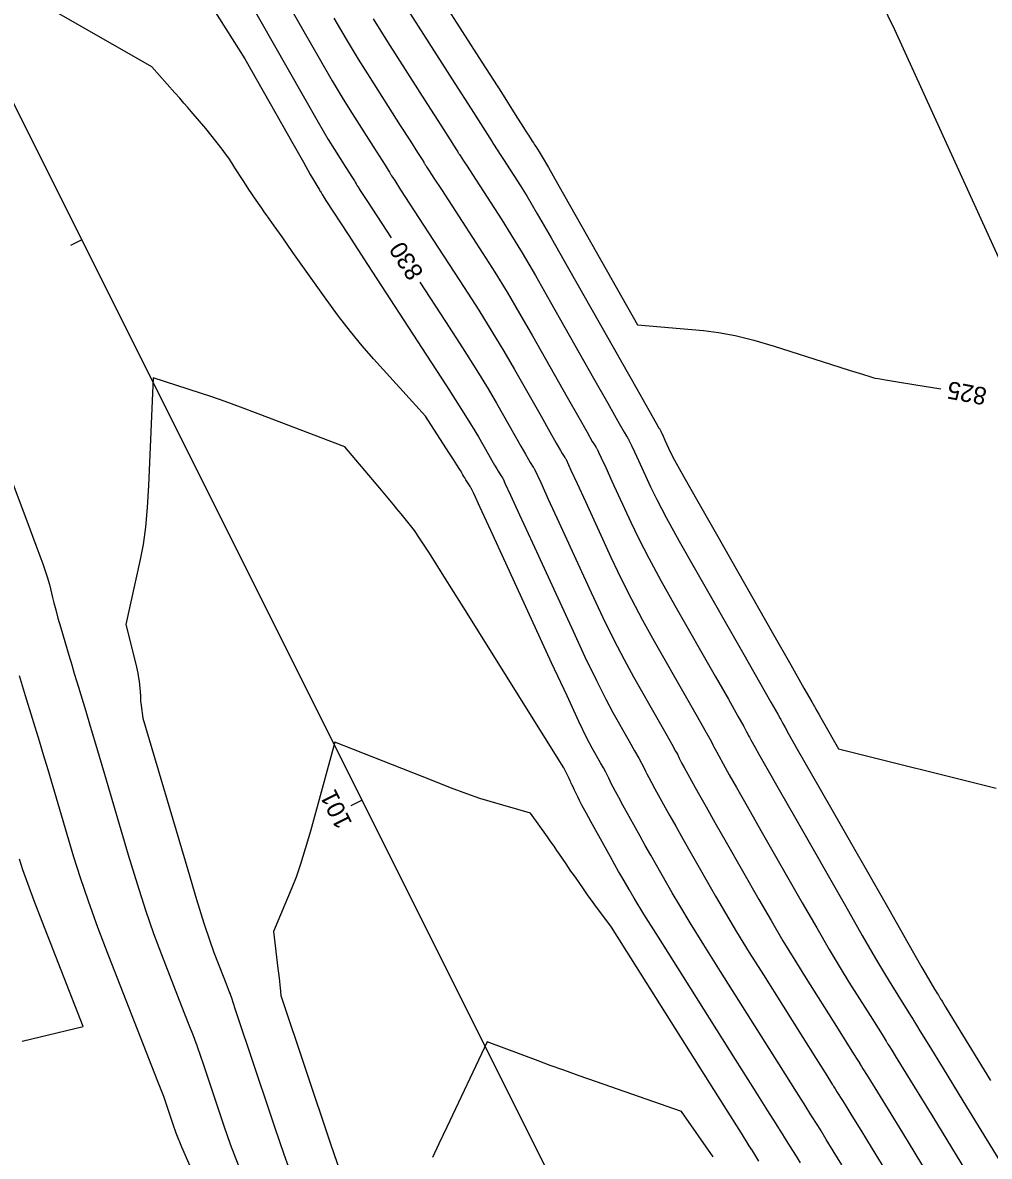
# Model space of a CAD drawing. Extents: x 1715724 to 1716561, y 394063 to 395906.
# Drawn here: x 1716294.8 to 1716371.9, y 394512.3 to 394602.7 of the extents above; entities that cross this region are included whole.
import ezdxf

# ---------------------------------------------------------------- set-up
doc = ezdxf.new("R2010")
doc.units = 0
for name, color, linetype in [('DT_X_Contour_Major', 7, 'Continuous'), ('DT_X_Contour_Minor', 7, 'Continuous'), ('DT_X_TIN_Hull', 7, 'Continuous'), ('GE_P_CL_10', 7, 'Continuous')]:
    doc.layers.add(name, color=color, linetype=linetype)

msp = doc.modelspace()

# ---------------------------------------------------------------- linework, layer by layer
at = {"layer": 'DT_X_Contour_Major'}
for points in [[(1716326.726, 394606.964), (1716331.443, 394599.586), (1716332.991, 394597.165), (1716334.098, 394595.434), (1716334.762, 394594.395), (1716334.985, 394594.046), (1716334.991, 394594.036), (1716335.003, 394594.017), (1716335.035, 394593.967), (1716335.087, 394593.885), (1716335.158, 394593.773), (1716335.376, 394593.433), (1716335.46, 394593.302), (1716335.55, 394593.162), (1716335.645, 394593.015), (1716335.746, 394592.86), (1716336.022, 394592.435), (1716336.255, 394592.043), (1716336.75, 394591.186), (1716337.504, 394589.863), (1716338.519, 394588.075), (1716343.863, 394578.642), (1716349.122, 394578.193), (1716350.319, 394578.042), (1716351.657, 394577.781), (1716353.136, 394577.41), (1716354.756, 394576.93), (1716359.263, 394575.503), (1716360.747, 394575.034), (1716361.82, 394574.696), (1716362.48, 394574.489), (1716362.728, 394574.414), (1716362.841, 394574.389), (1716363.065, 394574.35), (1716363.654, 394574.252), (1716364.608, 394574.096), (1716365.925, 394573.881), (1716368.057, 394573.535)], [(1716311.729, 394606.51), (1716315.871, 394599.191), (1716317.273, 394596.723), (1716318.373, 394594.806), (1716319.17, 394593.44), (1716319.665, 394592.626), (1716320.583, 394591.192), (1716321.113, 394590.36), (1716321.26, 394590.127), (1716321.328, 394590.016), (1716321.403, 394589.883), (1716321.43, 394589.836), (1716321.454, 394589.796), (1716321.475, 394589.761), (1716321.492, 394589.733), (1716321.535, 394589.667), (1716321.735, 394589.359), (1716322.304, 394588.484), (1716324.193, 394585.577)], [(1716326.482, 394582.056), (1716328.52, 394578.921), (1716329.893, 394576.795), (1716331.03, 394575), (1716331.931, 394573.535), (1716332.597, 394572.402), (1716334.059, 394569.821), (1716334.548, 394568.961), (1716334.916, 394568.316), (1716335.164, 394567.886), (1716335.292, 394567.672), (1716335.534, 394567.293), (1716335.579, 394567.222), (1716335.609, 394567.175), (1716335.623, 394567.151), (1716335.641, 394567.12), (1716336.134, 394566.052), (1716336.74, 394564.736), (1716337.586, 394562.897), (1716340.161, 394557.299), (1716341.097, 394555.303), (1716341.973, 394553.513), (1716342.789, 394551.931), (1716343.544, 394550.555), (1716345.48, 394547.161), (1716346.122, 394546.033), (1716346.596, 394545.193), (1716346.903, 394544.641), (1716347.043, 394544.379), (1716347.191, 394544.063), (1716347.271, 394543.902), (1716347.4, 394543.659), (1716347.577, 394543.333), (1716348.468, 394541.721), (1716348.809, 394541.112), (1716349.333, 394540.185), (1716350.04, 394538.943), (1716350.929, 394537.383), (1716353.545, 394532.803), (1716354.516, 394531.12), (1716355.469, 394529.507), (1716356.404, 394527.964), (1716357.32, 394526.491), (1716359.739, 394522.657), (1716361.103, 394520.494), (1716361.448, 394519.946), (1716361.568, 394519.755), (1716361.589, 394519.719), (1716361.611, 394519.682), (1716361.744, 394519.471), (1716361.854, 394519.295), (1716362.188, 394518.766), (1716362.458, 394518.33), (1716363.017, 394517.419), (1716363.866, 394516.033), (1716365.005, 394514.172), (1716368.426, 394508.576)], [(1716294.75, 394521.492), (1716299.62, 394522.654), (1716296.349, 394531.037), (1716295.71, 394532.694), (1716295.195, 394534.074), (1716294.806, 394535.176), (1716294.54, 394536.001)], [(1716349.893, 394512.258), (1716347.371, 394515.883), (1716340.593, 394518.247), (1716339.213, 394518.731), (1716337.978, 394519.17), (1716336.887, 394519.564), (1716335.941, 394519.913), (1716331.863, 394521.435), (1716328.645, 394514.631), (1716328.013, 394513.299), (1716327.498, 394512.22)]]:
    msp.add_lwpolyline(points, dxfattribs=at)
at = {"layer": 'DT_X_Contour_Minor'}
for points in [[(1716313.779, 394608.135), (1716317.231, 394602.036), (1716318.442, 394599.912), (1716319.487, 394598.113), (1716320.365, 394596.641), (1716321.078, 394595.494), (1716322.755, 394592.871), (1716323.71, 394591.375), (1716323.96, 394590.98), (1716324.059, 394590.822), (1716324.121, 394590.714), (1716324.145, 394590.672), (1716324.17, 394590.63), (1716324.197, 394590.586), (1716324.225, 394590.541), (1716324.303, 394590.42), (1716324.48, 394590.147), (1716324.953, 394589.419), (1716326.787, 394586.598), (1716330.021, 394581.624), (1716331.181, 394579.817), (1716332.237, 394578.124), (1716333.189, 394576.548), (1716334.037, 394575.086), (1716336.157, 394571.344), (1716336.86, 394570.105), (1716337.377, 394569.196), (1716337.709, 394568.617), (1716337.855, 394568.368), (1716338.047, 394568.067), (1716338.085, 394568.008), (1716338.111, 394567.966), (1716338.126, 394567.94), (1716338.152, 394567.895), (1716338.548, 394567.038), (1716339.03, 394565.993), (1716339.7, 394564.536), (1716341.739, 394560.104), (1716342.529, 394558.438), (1716343.368, 394556.765), (1716344.257, 394555.086), (1716345.196, 394553.399), (1716347.767, 394548.891), (1716348.615, 394547.401), (1716349.233, 394546.311), (1716349.621, 394545.621), (1716349.779, 394545.331), (1716349.891, 394545.092), (1716349.952, 394544.97), (1716350.049, 394544.786), (1716350.183, 394544.539), (1716350.859, 394543.318), (1716351.178, 394542.749), (1716351.76, 394541.724), (1716352.602, 394540.245), (1716353.706, 394538.31), (1716356.999, 394532.543), (1716358.159, 394530.525), (1716359.168, 394528.797), (1716360.027, 394527.358), (1716360.736, 394526.209), (1716362.426, 394523.53), (1716363.381, 394522.015), (1716363.624, 394521.629), (1716363.711, 394521.489), (1716363.736, 394521.446), (1716363.755, 394521.414), (1716363.851, 394521.26), (1716363.929, 394521.136), (1716364.162, 394520.767), (1716364.431, 394520.331), (1716365.064, 394519.299), (1716367.419, 394515.449), (1716371.528, 394508.729)], [(1716308.987, 394605.477), (1716312.517, 394599.871), (1716316.45, 394592.922), (1716317.194, 394591.607), (1716317.743, 394590.642), (1716318.096, 394590.026), (1716318.253, 394589.759), (1716318.466, 394589.425), (1716318.516, 394589.345), (1716318.559, 394589.273), (1716318.596, 394589.21), (1716318.686, 394589.052), (1716318.738, 394588.962), (1716318.752, 394588.937), (1716318.759, 394588.925), (1716318.766, 394588.914), (1716318.99, 394588.57), (1716320.76, 394585.847), (1716322.307, 394583.468), (1716327.02, 394576.219), (1716328.604, 394573.773), (1716329.822, 394571.875), (1716330.673, 394570.523), (1716331.158, 394569.717), (1716331.962, 394568.298), (1716332.236, 394567.816), (1716332.455, 394567.435), (1716332.62, 394567.155), (1716332.729, 394566.976), (1716332.949, 394566.633), (1716333.021, 394566.52), (1716333.074, 394566.437), (1716333.107, 394566.385), (1716333.12, 394566.363), (1716333.13, 394566.345), (1716333.28, 394566.022), (1716333.719, 394565.067), (1716334.45, 394563.479), (1716335.472, 394561.258), (1716338.584, 394554.494), (1716339.666, 394552.167), (1716340.578, 394550.261), (1716341.32, 394548.776), (1716341.893, 394547.711), (1716343.193, 394545.431), (1716343.628, 394544.664), (1716343.959, 394544.074), (1716344.185, 394543.662), (1716344.306, 394543.426), (1716344.491, 394543.033), (1716344.591, 394542.834), (1716344.75, 394542.532), (1716344.97, 394542.127), (1716345.25, 394541.618), (1716346.077, 394540.124), (1716346.44, 394539.474), (1716346.906, 394538.647), (1716347.477, 394537.641), (1716348.152, 394536.457), (1716350.09, 394533.062), (1716350.874, 394531.714), (1716351.771, 394530.217), (1716352.781, 394528.57), (1716353.905, 394526.774), (1716357.052, 394521.784), (1716358.086, 394520.145), (1716358.826, 394518.972), (1716359.272, 394518.264), (1716359.425, 394518.02), (1716359.441, 394517.992), (1716359.467, 394517.951), (1716359.532, 394517.847), (1716359.636, 394517.682), (1716359.779, 394517.454), (1716360.214, 394516.765), (1716360.485, 394516.329), (1716360.971, 394515.539), (1716361.673, 394514.394), (1716362.59, 394512.895), (1716365.324, 394508.424)], [(1716325.314, 394604.097), (1716329.271, 394597.907), (1716330.571, 394595.875), (1716332.062, 394593.541), (1716332.254, 394593.24), (1716332.273, 394593.205), (1716332.288, 394593.181), (1716332.319, 394593.132), (1716332.425, 394592.965), (1716332.608, 394592.68), (1716332.715, 394592.513), (1716332.901, 394592.227), (1716333.164, 394591.82), (1716334.521, 394589.733), (1716335.047, 394588.881), (1716335.86, 394587.499), (1716336.963, 394585.585), (1716338.354, 394583.14), (1716343.795, 394573.538), (1716344.759, 394571.837), (1716345.342, 394570.81), (1716345.544, 394570.455), (1716345.574, 394570.407), (1716345.601, 394570.364), (1716345.617, 394570.337), (1716345.634, 394570.306), (1716345.683, 394570.219), (1716345.72, 394570.147), (1716345.899, 394569.764), (1716346.043, 394569.453), (1716346.473, 394568.519), (1716346.824, 394567.844), (1716347.554, 394566.521), (1716348.663, 394564.55), (1716350.152, 394561.931), (1716354.627, 394554.083), (1716356.096, 394551.507), (1716357.146, 394549.666), (1716357.776, 394548.56), (1716357.987, 394548.189), (1716357.992, 394548.179), (1716357.994, 394548.175), (1716357.998, 394548.167), (1716358.003, 394548.157), (1716358.01, 394548.145), (1716358.03, 394548.109), (1716358.072, 394548.036), (1716358.182, 394547.843), (1716358.359, 394547.532), (1716358.606, 394547.101), (1716359.913, 394544.811), (1716372.498, 394541.671)], [(1716360.176, 394511.618), (1716359.48, 394512.755), (1716358.925, 394513.659), (1716358.511, 394514.329), (1716358.24, 394514.764), (1716357.704, 394515.613), (1716357.528, 394515.893), (1716357.401, 394516.094), (1716357.323, 394516.219), (1716357.294, 394516.265), (1716357.282, 394516.286), (1716357.096, 394516.581), (1716356.549, 394517.45), (1716355.638, 394518.894), (1716354.366, 394520.911), (1716350.489, 394527.056), (1716349.158, 394529.176), (1716348.072, 394530.927), (1716347.231, 394532.309), (1716346.635, 394533.322), (1716345.374, 394535.531), (1716344.914, 394536.339), (1716344.479, 394537.108), (1716344.07, 394537.837), (1716343.687, 394538.527), (1716342.698, 394540.313), (1716342.363, 394540.921), (1716342.101, 394541.405), (1716341.91, 394541.766), (1716341.791, 394542.004), (1716341.57, 394542.474), (1716341.466, 394542.682), (1716341.321, 394542.956), (1716341.134, 394543.296), (1716340.906, 394543.7), (1716340.241, 394544.866), (1716339.851, 394545.621), (1716339.183, 394547.009), (1716338.234, 394549.032), (1716337.006, 394551.689), (1716333.358, 394559.619), (1716332.16, 394562.222), (1716331.305, 394564.081), (1716330.792, 394565.197), (1716330.62, 394565.57), (1716330.618, 394565.574), (1716330.605, 394565.594), (1716330.568, 394565.651), (1716330.508, 394565.746), (1716330.423, 394565.878), (1716330.166, 394566.281), (1716330.075, 394566.425), (1716329.995, 394566.555), (1716329.924, 394566.672), (1716329.864, 394566.775), (1716329.719, 394567.033), (1716329.62, 394567.194), (1716329.435, 394567.487), (1716329.164, 394567.909), (1716328.805, 394568.463), (1716326.928, 394571.349), (1716322.786, 394575.931), (1716321.885, 394576.965), (1716320.956, 394578.104), (1716320, 394579.347), (1716319.017, 394580.694), (1716316.36, 394584.426), (1716315.487, 394585.653), (1716314.86, 394586.533), (1716314.481, 394587.066), (1716314.349, 394587.253), (1716314.325, 394587.291), (1716314.29, 394587.342), (1716314.203, 394587.467), (1716314.064, 394587.667), (1716313.872, 394587.941), (1716313.291, 394588.769), (1716313.07, 394589.089), (1716312.843, 394589.427), (1716312.611, 394589.784), (1716312.372, 394590.158), (1716311.728, 394591.181), (1716311.482, 394591.561), (1716311.228, 394591.933), (1716310.966, 394592.298), (1716310.694, 394592.655), (1716309.41, 394594.306), (1716308.234, 394595.673), (1716307.965, 394595.985), (1716307.66, 394596.336), (1716307.318, 394596.725), (1716306.942, 394597.151), (1716305.1, 394599.233), (1716297.709, 394603.453)], [(1716319.611, 394603.101), (1716320.601, 394601.421), (1716321.561, 394599.841), (1716322.49, 394598.362), (1716324.927, 394594.55), (1716325.729, 394593.295), (1716326.307, 394592.39), (1716326.661, 394591.834), (1716326.791, 394591.628), (1716326.838, 394591.544), (1716326.859, 394591.508), (1716326.886, 394591.464), (1716326.919, 394591.411), (1716326.959, 394591.349), (1716327.071, 394591.173), (1716327.225, 394590.936), (1716327.602, 394590.355), (1716328.203, 394589.431), (1716329.026, 394588.164), (1716331.521, 394584.327), (1716332.47, 394582.838), (1716333.445, 394581.249), (1716334.447, 394579.56), (1716335.476, 394577.771), (1716338.255, 394572.866), (1716339.171, 394571.249), (1716339.837, 394570.076), (1716340.253, 394569.348), (1716340.418, 394569.064), (1716340.524, 394568.898), (1716340.56, 394568.84), (1716340.59, 394568.793), (1716340.613, 394568.756), (1716340.629, 394568.729), (1716340.662, 394568.67), (1716340.744, 394568.497), (1716340.963, 394568.024), (1716341.32, 394567.25), (1716341.814, 394566.175), (1716343.317, 394562.909), (1716343.96, 394561.573), (1716344.763, 394560.017), (1716345.726, 394558.241), (1716346.848, 394556.243), (1716350.054, 394550.622), (1716351.109, 394548.77), (1716351.871, 394547.429), (1716352.34, 394546.601), (1716352.515, 394546.284), (1716352.592, 394546.121), (1716352.633, 394546.039), (1716352.699, 394545.913), (1716352.79, 394545.745), (1716352.906, 394545.534), (1716353.249, 394544.915), (1716353.548, 394544.386), (1716354.186, 394543.263), (1716355.165, 394541.546), (1716356.484, 394539.236), (1716360.454, 394532.283), (1716361.801, 394529.931), (1716362.867, 394528.087), (1716363.65, 394526.752), (1716364.152, 394525.926), (1716365.113, 394524.403), (1716365.429, 394523.901), (1716365.658, 394523.537), (1716365.8, 394523.311), (1716365.855, 394523.223), (1716365.883, 394523.173), (1716365.899, 394523.146), (1716365.924, 394523.105), (1716365.959, 394523.049), (1716366.004, 394522.977), (1716366.136, 394522.768), (1716366.404, 394522.331), (1716367.11, 394521.179), (1716368.253, 394519.31), (1716369.833, 394516.726), (1716374.631, 394508.881)], [(1716322.756, 394603.042), (1716323.902, 394601.229), (1716327.099, 394596.229), (1716328.15, 394594.585), (1716328.904, 394593.405), (1716329.361, 394592.688), (1716329.522, 394592.434), (1716329.556, 394592.375), (1716329.574, 394592.344), (1716329.602, 394592.298), (1716329.642, 394592.236), (1716329.692, 394592.157), (1716329.839, 394591.927), (1716329.97, 394591.724), (1716330.251, 394591.291), (1716330.683, 394590.626), (1716331.266, 394589.729), (1716333.021, 394587.03), (1716333.758, 394585.86), (1716334.653, 394584.374), (1716335.705, 394582.573), (1716336.915, 394580.455), (1716340.352, 394574.389), (1716341.483, 394572.394), (1716342.298, 394570.957), (1716342.798, 394570.079), (1716342.981, 394569.759), (1716343.049, 394569.652), (1716343.074, 394569.614), (1716343.095, 394569.579), (1716343.115, 394569.547), (1716343.131, 394569.518), (1716343.173, 394569.445), (1716343.232, 394569.322), (1716343.377, 394569.01), (1716343.61, 394568.507), (1716343.929, 394567.814), (1716344.895, 394565.714), (1716345.392, 394564.709), (1716346.158, 394563.269), (1716347.194, 394561.396), (1716348.5, 394559.087), (1716352.34, 394552.352), (1716353.603, 394550.138), (1716354.508, 394548.548), (1716355.058, 394547.58), (1716355.251, 394547.236), (1716355.292, 394547.15), (1716355.314, 394547.107), (1716355.349, 394547.04), (1716355.397, 394546.951), (1716355.458, 394546.84), (1716355.64, 394546.512), (1716355.917, 394546.023), (1716356.613, 394544.802), (1716357.728, 394542.848), (1716359.261, 394540.162), (1716363.908, 394532.024), (1716365.444, 394529.336), (1716366.566, 394527.377), (1716367.274, 394526.146), (1716367.567, 394525.644), (1716367.799, 394525.276), (1716367.877, 394525.153), (1716367.936, 394525.059), (1716367.976, 394524.993), (1716367.998, 394524.957), (1716368.03, 394524.899), (1716368.043, 394524.878), (1716368.055, 394524.857), (1716368.067, 394524.838), (1716368.079, 394524.818), (1716368.11, 394524.769), (1716368.194, 394524.633), (1716368.42, 394524.262), (1716368.79, 394523.657), (1716369.304, 394522.818), (1716372.033, 394518.354)], [(1716356.878, 394511.779), (1716356.538, 394512.328), (1716356.266, 394512.763), (1716355.629, 394513.772), (1716355.42, 394514.104), (1716355.27, 394514.342), (1716355.179, 394514.487), (1716355.147, 394514.539), (1716355.139, 394514.552), (1716354.921, 394514.899), (1716354.271, 394515.929), (1716353.191, 394517.642), (1716351.679, 394520.038), (1716347.073, 394527.339), (1716345.535, 394529.782), (1716344.373, 394531.637), (1716343.588, 394532.904), (1716343.181, 394533.582), (1716342.597, 394534.604), (1716342.351, 394535.037), (1716342.053, 394535.569), (1716341.701, 394536.2), (1716341.296, 394536.93), (1716340.146, 394539.007), (1716339.757, 394539.715), (1716339.451, 394540.278), (1716339.229, 394540.698), (1716339.091, 394540.975), (1716338.834, 394541.521), (1716338.748, 394541.703), (1716338.684, 394541.838), (1716338.641, 394541.927), (1716338.619, 394541.97), (1716338.589, 394542.022), (1716338.568, 394542.063), (1716338.529, 394542.146), (1716338.471, 394542.27), (1716338.394, 394542.437), (1716337.991, 394543.312), (1716329.949, 394556.15), (1716328.412, 394558.592), (1716327.25, 394560.419), (1716326.462, 394561.629), (1716326.049, 394562.222), (1716324.992, 394563.553), (1716324.63, 394563.997), (1716324.488, 394564.169), (1716324.215, 394564.494), (1716323.813, 394564.971), (1716323.28, 394565.602), (1716320.492, 394568.903), (1716313.569, 394571.543), (1716312.17, 394572.071), (1716310.938, 394572.523), (1716309.874, 394572.898), (1716308.978, 394573.198), (1716305.189, 394574.419), (1716304.824, 394565.823), (1716304.725, 394564.072), (1716304.583, 394562.504), (1716304.399, 394561.12), (1716304.173, 394559.918), (1716303.017, 394554.736), (1716303.729, 394551.886), (1716303.866, 394551.324), (1716303.969, 394550.859), (1716304.04, 394550.492), (1716304.079, 394550.221), (1716304.138, 394549.629), (1716304.158, 394549.426), (1716304.171, 394549.259), (1716304.179, 394549.13), (1716304.181, 394549.037), (1716304.179, 394548.84), (1716304.182, 394548.749), (1716304.193, 394548.622), (1716304.211, 394548.459), (1716304.237, 394548.261), (1716304.377, 394547.254), (1716307.962, 394535.155), (1716308.668, 394532.798), (1716309.251, 394530.914), (1716309.71, 394529.503), (1716310.046, 394528.564), (1716310.777, 394526.691), (1716311.018, 394526.075), (1716311.19, 394525.632), (1716311.295, 394525.362), (1716311.333, 394525.266), (1716311.342, 394525.239), (1716311.439, 394524.947), (1716311.726, 394524.091), (1716312.202, 394522.671), (1716312.866, 394520.688), (1716314.891, 394514.647), (1716315.63, 394512.491), (1716316.331, 394510.553)], [(1716291.309, 394573.065), (1716295.115, 394563.009), (1716295.84, 394561.075), (1716296.383, 394559.584), (1716296.744, 394558.534), (1716296.925, 394557.927), (1716297.163, 394556.896), (1716297.271, 394556.455), (1716297.418, 394555.906), (1716297.603, 394555.248), (1716297.826, 394554.481), (1716298.473, 394552.29), (1716298.702, 394551.515), (1716298.905, 394550.83), (1716299.083, 394550.238), (1716299.234, 394549.737), (1716299.603, 394548.522), (1716299.814, 394547.822), (1716300.169, 394546.633), (1716300.668, 394544.953), (1716301.311, 394542.785), (1716303.217, 394536.349), (1716303.919, 394534.044), (1716304.593, 394531.954), (1716305.239, 394530.08), (1716305.858, 394528.421), (1716307.472, 394524.286), (1716308.002, 394522.929), (1716308.381, 394521.957), (1716308.609, 394521.372), (1716308.686, 394521.173), (1716308.692, 394521.156), (1716308.751, 394520.979), (1716308.925, 394520.461), (1716309.213, 394519.602), (1716309.615, 394518.402), (1716310.84, 394514.745), (1716311.357, 394513.28), (1716311.99, 394511.625)], [(1716308.147, 394511.511), (1716307.499, 394513.044), (1716307.047, 394514.155), (1716306.789, 394514.843), (1716306.04, 394517.079), (1716305.571, 394518.282), (1716301.67, 394528.278), (1716300.793, 394530.571), (1716300.036, 394532.651), (1716299.398, 394534.519), (1716298.879, 394536.175), (1716297.214, 394541.789), (1716296.813, 394543.134), (1716296.45, 394544.343), (1716296.125, 394545.416), (1716295.021, 394549.049), (1716294.541, 394550.645)], [(1716353.555, 394511.931), (1716353.313, 394512.315), (1716353.139, 394512.589), (1716353.035, 394512.755), (1716352.999, 394512.812), (1716352.996, 394512.818), (1716352.784, 394513.153), (1716352.153, 394514.154), (1716351.102, 394515.821), (1716349.63, 394518.153), (1716341.783, 394530.593), (1716340.46, 394532.378), (1716340.186, 394532.749), (1716339.933, 394533.096), (1716339.701, 394533.42), (1716339.489, 394533.72), (1716338.95, 394534.491), (1716338.749, 394534.779), (1716338.55, 394535.068), (1716338.352, 394535.357), (1716338.156, 394535.645), (1716337.634, 394536.414), (1716337.427, 394536.716), (1716337.197, 394537.049), (1716336.942, 394537.41), (1716336.665, 394537.8), (1716335.315, 394539.691), (1716332.096, 394540.609), (1716331.286, 394540.862), (1716330.235, 394541.229), (1716328.944, 394541.71), (1716327.412, 394542.304), (1716319.699, 394545.343), (1716317.746, 394538.257), (1716317.34, 394536.835), (1716316.96, 394535.606), (1716316.605, 394534.569), (1716316.275, 394533.725), (1716314.795, 394530.234), (1716315.152, 394527.29), (1716315.221, 394526.721), (1716315.273, 394526.276), (1716315.311, 394525.955), (1716315.332, 394525.759), (1716315.395, 394525.132), (1716319.359, 394513.301), (1716320.139, 394511)]]:
    msp.add_lwpolyline(points, dxfattribs=at)
at = {"layer": 'DT_X_TIN_Hull'}
msp.add_lwpolyline([(1716375.711, 394577.402), (1716364.4, 394602.185), (1716352.803, 394625.988), (1716362.292, 394649.196), (1716385.754, 394645.713)], dxfattribs=at)
at = {"layer": 'GE_P_CL_10'}
for p, q in [((1716447.809, 394289.082), (1716249.46, 394685.42)), ((1716299.499, 394585.433), (1716298.605, 394584.985)), ((1716321.876, 394540.719), (1716320.982, 394540.272))]:
    msp.add_line(p, q, dxfattribs=at)

# ---------------------------------------------------------------- texts
at = {"layer": 'DT_X_Contour_Major'}
for s, rotation, p in [('830', 123.02972, (1716326.832, 394582.802)), ('825', 169.44823, (1716371.813, 394573.591))]:
    msp.add_text(s, height=1.4, rotation=rotation, dxfattribs=at).set_placement(p)
at = {"layer": 'GE_P_CL_10'}
msp.add_text('101', height=1.4, rotation=116.58573, dxfattribs=at).set_placement((1716321.114, 394538.891))

doc.saveas('drawing.dxf')
